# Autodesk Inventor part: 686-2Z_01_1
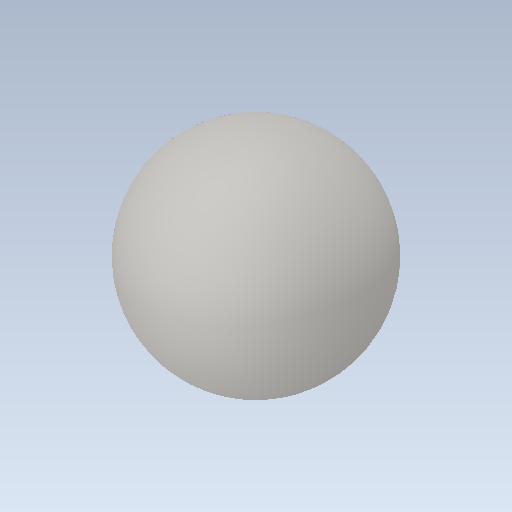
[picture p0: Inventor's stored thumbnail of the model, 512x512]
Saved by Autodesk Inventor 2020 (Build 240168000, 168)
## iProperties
Created: 2017-11
Part Number: 686-2Z_01_1
Material: Ogólny
Document SubType Name: Modeling
Designer: Tomasz
Density: 1 g/cm^3
Appearance: Domyślna
Sending System: SolidWorks 2017
Last Author: Tomasz
Last Saved: 2017-11-19
Source: 686-2Z_01_1
Author: Tomasz
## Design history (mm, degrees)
feature "Imported1"
node "Bryła1"
